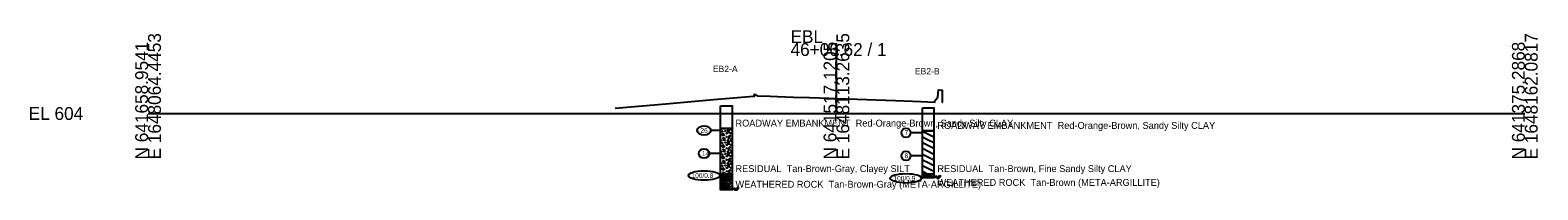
# Model space of a CAD drawing. Extents: x -26 to 303, y -74 to 518.
# Drawn here: x -25.7 to 302.8, y 483.4 to 518.1 of the extents above; entities that cross this region are included whole.
import ezdxf

# ---------------------------------------------------------------- set-up
doc = ezdxf.new("R2010")
doc.units = 0
for name, color, linetype in [('Exist Cross Section Cell', 7, 'Continuous'), ('Exist XS Ground Line', 7, 'Continuous'), ('Prop Road Sect_ Boring - Header Labels from Geopak', 7, 'Continuous'), ('Prop Road Sect_ Boring - Material (Desc Tx)', 7, 'Continuous'), ('Prop Road Sect_ Boring - Material (Outline)', 7, 'Continuous'), ('Prop Road Sect_ Boring - Peripheral (HR Indicator)', 7, 'Continuous'), ('Prop Road Sect_ Boring - Peripheral (SPT Oval + Leader)', 7, 'Continuous'), ('Prop Road Sect_ Boring - Peripheral (SPT Tx)', 7, 'Continuous')]:
    doc.layers.add(name, color=color, linetype=linetype)

msp = doc.modelspace()

# ---------------------------------------------------------------- linework, layer by layer
at = {"layer": 'Exist Cross Section Cell'}
for p, q in [((150, 500), (150, 515.32)), ((0, 500), (150, 500)), ((150, 500), (300, 500))]:
    msp.add_line(p, q, dxfattribs=at)
at = {"layer": 'Exist XS Ground Line'}
msp.add_lwpolyline([(101.79, 501.17), (112.83, 502.12), (123.23, 503.02), (126.72, 503.32), (131.08, 503.7), (131.75, 503.75), (132.14, 503.79), (132.14, 504.19), (132.85, 503.85), (135.59, 503.75), (137.14, 503.7), (140.61, 503.57), (144.15, 503.45), (148.37, 503.3), (150, 503.24), (150, 503.24), (154.5, 503.09), (162.86, 502.79), (168.39, 502.6), (171.44, 502.49), (171.44, 502.74), (172.06, 503.52), (172.24, 505.11), (173.04, 505.1), (173.05, 502.43), (173.18, 502.43)], dxfattribs=at)
msp.add_lwpolyline([(101.79, 501.17), (112.83, 502.12), (123.23, 503.02), (126.72, 503.32), (131.08, 503.7), (131.75, 503.75), (132.14, 503.79), (132.14, 504.19), (132.85, 503.85), (135.59, 503.75), (137.14, 503.7), (140.61, 503.57), (144.15, 503.45), (148.37, 503.3), (150, 503.24), (150, 503.24), (154.5, 503.09), (162.86, 502.79), (168.39, 502.6), (171.44, 502.49), (171.44, 502.74), (172.06, 503.52), (172.24, 505.11), (173.04, 505.1), (173.05, 502.43), (173.18, 502.43)], dxfattribs=at)
at = {"layer": 'Prop Road Sect_ Boring - Material (Outline)'}
for p, q in [((125.32, 496.7), (125.25, 496.62)), ((125.32, 496.7), (125.25, 496.62)), ((125.65, 496.48), (125.65, 496.7)), ((125.65, 496.48), (125.65, 496.7)), ((168.75, 496.17), (171.25, 494.92)), ((168.75, 496.17), (171.25, 494.92)), ((168.75, 496.17), (171.25, 494.92)), ((168.75, 496.17), (171.25, 494.92)), ((171.18, 496.2), (171.25, 496.17)), ((171.18, 496.2), (171.25, 496.17)), ((171.25, 496.17), (171.25, 496.16)), ((171.25, 496.17), (171.25, 496.16)), ((171.25, 496.17), (171.25, 496.16)), ((171.25, 496.17), (171.25, 496.16)), ((125.39, 494.29), (125.25, 494.12)), ((125.39, 494.29), (125.25, 494.12)), ((125.65, 493.98), (125.65, 494.29)), ((125.65, 493.98), (125.65, 494.29)), ((168.75, 494.92), (170, 494.29)), ((168.75, 494.92), (170, 494.29)), ((168.75, 493.67), (171.25, 492.42)), ((168.75, 493.67), (171.25, 492.42)), ((168.75, 493.67), (171.25, 492.42)), ((168.75, 493.67), (171.25, 492.42)), ((170, 494.29), (171.25, 493.67)), ((170, 494.29), (171.25, 493.67)), ((171.25, 494.92), (171.25, 494.92)), ((171.25, 494.92), (171.25, 494.92)), ((171.25, 493.67), (171.25, 493.67)), ((171.25, 493.67), (171.25, 493.67)), ((171.25, 493.67), (171.25, 493.67)), ((171.25, 493.67), (171.25, 493.67)), ((125.39, 491.8), (125.25, 491.63)), ((125.39, 491.8), (125.25, 491.63)), ((125.65, 491.48), (125.65, 491.8)), ((125.65, 491.48), (125.65, 491.8)), ((168.75, 492.42), (170, 491.8)), ((168.75, 492.42), (170, 491.8)), ((168.75, 491.17), (171.25, 489.92)), ((168.75, 491.17), (171.25, 489.92)), ((168.75, 491.17), (171.25, 489.92)), ((168.75, 491.17), (171.25, 489.92)), ((168.75, 489.92), (170, 489.3)), ((168.75, 489.92), (170, 489.3)), ((170, 491.8), (171.25, 491.17)), ((170, 491.8), (171.25, 491.17)), ((171.25, 492.42), (171.25, 492.42)), ((171.25, 492.42), (171.25, 492.42)), ((171.25, 491.17), (171.25, 491.17)), ((171.25, 491.17), (171.25, 491.17)), ((171.25, 491.17), (171.25, 491.17)), ((171.25, 491.17), (171.25, 491.17)), ((171.25, 489.92), (171.25, 489.92)), ((171.25, 489.92), (171.25, 489.92)), ((124.83, 486.8), (124.75, 486.76)), ((124.83, 486.8), (124.75, 486.76)), ((124.79, 486.6), (125.01, 486.6)), ((124.79, 486.6), (125.01, 486.6)), ((124.79, 486.51), (124.99, 486.51)), ((124.79, 486.51), (124.99, 486.51)), ((124.94, 486.74), (124.85, 486.8)), ((124.94, 486.74), (124.85, 486.8)), ((125.39, 489.3), (125.25, 489.13)), ((125.39, 489.3), (125.25, 489.13)), ((125.65, 488.98), (125.65, 489.3)), ((125.65, 488.98), (125.65, 489.3)), ((126.34, 486.68), (126.84, 486.68)), ((126.34, 486.68), (126.84, 486.68)), ((126.41, 486.57), (126.81, 486.57)), ((126.41, 486.57), (126.81, 486.57)), ((126.46, 486.46), (126.74, 486.46)), ((126.46, 486.46), (126.74, 486.46)), ((127.25, 486.76), (127.25, 486.76)), ((127.25, 486.76), (127.25, 486.76)), ((168.75, 488.67), (171.25, 487.42)), ((168.75, 488.67), (171.25, 487.42)), ((168.75, 488.67), (171.25, 487.42)), ((168.75, 488.67), (171.25, 487.42)), ((168.75, 487.42), (170, 486.8)), ((168.75, 487.42), (170, 486.8)), ((168.75, 486.11), (169.32, 486.24)), ((168.75, 486.11), (169.32, 486.24)), ((168.79, 486.7), (169.01, 486.7)), ((168.79, 486.7), (169.01, 486.7)), ((168.79, 486.61), (168.99, 486.61)), ((168.79, 486.61), (168.99, 486.61)), ((169.32, 486.24), (168.89, 486)), ((169.32, 486.24), (168.89, 486)), ((170.29, 486.25), (169.65, 486)), ((170.29, 486.25), (169.65, 486)), ((170.58, 486.25), (169.94, 486)), ((170.58, 486.25), (169.94, 486)), ((170, 489.3), (171.25, 488.67)), ((170, 489.3), (171.25, 488.67)), ((170.09, 486.25), (170.29, 486.25)), ((170.09, 486.25), (170.29, 486.25)), ((170.58, 486.25), (170.11, 486)), ((170.58, 486.25), (170.11, 486)), ((170.34, 486.78), (170.84, 486.78)), ((170.34, 486.78), (170.84, 486.78)), ((170.41, 486.67), (170.81, 486.67)), ((170.41, 486.67), (170.81, 486.67)), ((170.46, 486.56), (170.74, 486.56)), ((170.46, 486.56), (170.74, 486.56)), ((171.25, 488.67), (171.25, 488.67)), ((171.25, 488.67), (171.25, 488.67)), ((171.25, 488.67), (171.25, 488.67)), ((171.25, 488.67), (171.25, 488.67)), ((171.25, 487.42), (171.25, 487.42)), ((171.25, 487.42), (171.25, 487.42)), ((171.25, 486.26), (171.25, 486.27)), ((171.25, 486.26), (171.25, 486.27)), ((124.75, 486), (125.32, 486.14)), ((124.75, 486), (125.32, 486.14)), ((124.86, 484.85), (124.75, 484.94)), ((124.86, 484.85), (124.75, 484.94)), ((124.75, 483.51), (125.32, 483.64)), ((124.75, 483.51), (125.32, 483.64)), ((124.79, 484.1), (125.01, 484.1)), ((124.79, 484.1), (125.01, 484.1)), ((124.79, 484.01), (124.99, 484.01)), ((124.79, 484.01), (124.99, 484.01)), ((125.32, 486.14), (124.89, 485.9)), ((125.32, 486.14), (124.89, 485.9)), ((125.32, 483.64), (124.89, 483.4)), ((125.32, 483.64), (124.89, 483.4)), ((125.19, 485.84), (125.21, 485.9)), ((125.19, 485.84), (125.21, 485.9)), ((125.37, 485.28), (125.56, 485.28)), ((125.37, 485.28), (125.56, 485.28)), ((125.39, 485.34), (125.6, 485.34)), ((125.39, 485.34), (125.6, 485.34)), ((125.39, 485.22), (125.61, 485.22)), ((125.39, 485.22), (125.61, 485.22)), ((125.42, 485.39), (125.69, 485.39)), ((125.42, 485.39), (125.69, 485.39)), ((125.59, 485.84), (125.65, 485.9)), ((125.59, 485.84), (125.65, 485.9)), ((126.29, 486.14), (125.65, 485.9)), ((126.29, 486.14), (125.65, 485.9)), ((126.29, 483.65), (125.65, 483.4)), ((126.29, 483.65), (125.65, 483.4)), ((125.69, 486.02), (125.97, 486.02)), ((125.69, 486.02), (125.97, 486.02)), ((125.69, 483.53), (125.97, 483.53)), ((125.69, 483.53), (125.97, 483.53)), ((125.87, 486.09), (126.15, 486.09)), ((125.87, 486.09), (126.15, 486.09)), ((125.87, 483.59), (126.15, 483.59)), ((125.87, 483.59), (126.15, 483.59)), ((126.58, 486.14), (125.94, 485.9)), ((126.58, 486.14), (125.94, 485.9)), ((126.58, 483.65), (125.94, 483.4)), ((126.58, 483.65), (125.94, 483.4)), ((126.04, 485.84), (126.11, 485.9)), ((126.04, 485.84), (126.11, 485.9)), ((126.09, 486.14), (126.29, 486.14)), ((126.09, 486.14), (126.29, 486.14)), ((126.09, 483.65), (126.29, 483.65)), ((126.09, 483.65), (126.29, 483.65)), ((126.58, 486.14), (126.11, 485.9)), ((126.58, 486.14), (126.11, 485.9)), ((126.58, 483.65), (126.11, 483.4)), ((126.58, 483.65), (126.11, 483.4)), ((126.26, 484.66), (126.54, 484.66)), ((126.26, 484.66), (126.54, 484.66)), ((126.26, 484.58), (126.51, 484.58)), ((126.26, 484.58), (126.51, 484.58)), ((126.31, 484.49), (126.49, 484.49)), ((126.31, 484.49), (126.49, 484.49)), ((126.34, 484.18), (126.84, 484.18)), ((126.34, 484.18), (126.84, 484.18)), ((126.41, 484.07), (126.81, 484.07)), ((126.41, 484.07), (126.81, 484.07)), ((126.46, 483.96), (126.74, 483.96)), ((126.46, 483.96), (126.74, 483.96)), ((127.25, 485.93), (127.13, 485.9)), ((127.25, 485.93), (127.13, 485.9)), ((127.25, 483.43), (127.13, 483.4)), ((127.25, 483.43), (127.13, 483.4)), ((127.25, 486.16), (127.25, 486.16)), ((127.25, 486.16), (127.25, 486.16)), ((127.25, 486), (127.25, 486.01)), ((127.25, 486), (127.25, 486.01)), ((127.25, 485.47), (127.25, 485.47)), ((127.25, 485.47), (127.25, 485.47)), ((127.25, 484.94), (127.25, 484.94)), ((127.25, 484.94), (127.25, 484.94)), ((127.25, 484.26), (127.25, 484.26)), ((127.25, 484.26), (127.25, 484.26)), ((127.25, 483.66), (127.25, 483.67)), ((127.25, 483.66), (127.25, 483.67)), ((127.25, 483.51), (127.25, 483.51)), ((127.25, 483.51), (127.25, 483.51)), ((169.69, 486.13), (169.97, 486.13)), ((169.69, 486.13), (169.97, 486.13)), ((169.87, 486.19), (170.15, 486.19)), ((169.87, 486.19), (170.15, 486.19)), ((171.25, 486.03), (171.13, 486)), ((171.25, 486.03), (171.13, 486)), ((171.25, 486.11), (171.25, 486.11)), ((171.25, 486.11), (171.25, 486.11))]:
    msp.add_line(p, q, dxfattribs=at)
for points in [[(124.75, 501.7), (127.25, 501.7), (127.25, 496.7), (124.75, 496.7)], [(168.75, 501.2), (171.25, 501.2), (171.25, 496.2), (168.75, 496.2)], [(124.75, 496.7), (127.25, 496.7), (127.25, 486.8), (124.75, 486.8)], [(168.75, 496.2), (171.25, 496.2), (171.25, 486.8), (168.75, 486.8)], [(124.75, 486.8), (127.25, 486.8), (127.25, 483.4), (124.75, 483.4)], [(168.75, 486.8), (171.25, 486.8), (171.25, 486), (168.75, 486)]]:
    msp.add_lwpolyline(points, close=True, dxfattribs=at)
for points in [[(126.58, 496.48), (126.58, 495.86), (126.14, 496.3)], [(126.58, 496.48), (126.58, 495.86), (126.14, 496.3)], [(125.29, 495.06), (125.29, 495.68), (125.69, 495.2)], [(125.29, 495.06), (125.29, 495.68), (125.69, 495.2)], [(125.29, 492.56), (125.29, 493.18), (125.69, 492.7)], [(125.29, 492.56), (125.29, 493.18), (125.69, 492.7)], [(125.65, 494.29), (125.65, 494.6), (125.39, 494.29)], [(125.65, 494.29), (125.65, 494.6), (125.39, 494.29)], [(126.58, 493.99), (126.58, 493.36), (126.14, 493.8)], [(126.58, 493.99), (126.58, 493.36), (126.14, 493.8)], [(126.47, 495.06), (126.47, 494.43), (126.91, 494.87)], [(126.47, 495.06), (126.47, 494.43), (126.91, 494.87)], [(125.29, 490.06), (125.29, 490.69), (125.69, 490.21)], [(125.29, 490.06), (125.29, 490.69), (125.69, 490.21)], [(125.65, 491.8), (125.65, 492.11), (125.39, 491.8)], [(125.65, 491.8), (125.65, 492.11), (125.39, 491.8)], [(125.65, 489.3), (125.65, 489.61), (125.39, 489.3)], [(125.65, 489.3), (125.65, 489.61), (125.39, 489.3)], [(126.58, 491.49), (126.58, 490.86), (126.14, 491.31)], [(126.58, 491.49), (126.58, 490.86), (126.14, 491.31)], [(126.47, 492.56), (126.47, 491.93), (126.91, 492.38)], [(126.47, 492.56), (126.47, 491.93), (126.91, 492.38)], [(126.47, 490.06), (126.47, 489.44), (126.91, 489.88)], [(126.47, 490.06), (126.47, 489.44), (126.91, 489.88)], [(124.75, 486.16), (125.02, 486.26), (125.4, 486.38), (125.84, 486.53), (125.79, 486.41), (125.75, 486.36), (126.34, 486.51)], [(124.75, 486.16), (125.02, 486.26), (125.4, 486.38), (125.84, 486.53), (125.79, 486.41), (125.75, 486.36), (126.34, 486.51)], [(125.27, 486.8), (125.14, 486.65), (125.09, 486.62), (124.94, 486.74)], [(125.27, 486.8), (125.14, 486.65), (125.09, 486.62), (124.94, 486.74)], [(125.21, 485.9), (125.64, 486.2), (126.34, 486.37), (126.71, 486.43), (127.14, 486.68), (127.25, 486.76)], [(125.21, 485.9), (125.64, 486.2), (126.34, 486.37), (126.71, 486.43), (127.14, 486.68), (127.25, 486.76)], [(125.29, 487.56), (125.29, 488.19), (125.69, 487.71)], [(125.29, 487.56), (125.29, 488.19), (125.69, 487.71)], [(125.65, 486.8), (125.65, 487.11), (125.39, 486.8)], [(125.65, 486.8), (125.65, 487.11), (125.39, 486.8)], [(125.57, 486.8), (125.56, 486.79), (125.54, 486.76), (125.56, 486.74), (125.74, 486.79), (125.76, 486.8)], [(125.57, 486.8), (125.56, 486.79), (125.54, 486.76), (125.56, 486.74), (125.74, 486.79), (125.76, 486.8)], [(126.58, 488.99), (126.58, 488.37), (126.14, 488.81)], [(126.58, 488.99), (126.58, 488.37), (126.14, 488.81)], [(126.47, 487.56), (126.47, 486.94), (126.91, 487.38)], [(126.47, 487.56), (126.47, 486.94), (126.91, 487.38)], [(168.75, 486.26), (169.02, 486.36), (169.4, 486.48), (169.84, 486.63), (169.79, 486.51), (169.75, 486.46), (170.34, 486.62)], [(168.75, 486.26), (169.02, 486.36), (169.4, 486.48), (169.84, 486.63), (169.79, 486.51), (169.75, 486.46), (170.34, 486.62)], [(169.18, 486.8), (169.14, 486.75), (169.09, 486.73), (168.99, 486.8)], [(169.18, 486.8), (169.14, 486.75), (169.09, 486.73), (168.99, 486.8)], [(169.21, 486), (169.64, 486.3), (170.34, 486.47), (170.71, 486.53), (171.14, 486.78), (171.16, 486.8)], [(169.21, 486), (169.64, 486.3), (170.34, 486.47), (170.71, 486.53), (171.14, 486.78), (171.16, 486.8)], [(171.25, 486.26), (171.19, 486.25), (170.86, 486.16), (170.8, 486)], [(171.25, 486.26), (171.19, 486.25), (170.86, 486.16), (170.8, 486)], [(124.97, 485.44), (124.87, 485.49), (124.8, 485.49), (124.75, 485.47)], [(124.97, 485.44), (124.87, 485.49), (124.8, 485.49), (124.75, 485.47)], [(124.94, 484.24), (124.85, 484.31), (124.75, 484.26)], [(124.94, 484.24), (124.85, 484.31), (124.75, 484.26)], [(124.75, 483.66), (125.02, 483.76), (125.4, 483.88), (125.84, 484.03), (125.79, 483.91), (125.75, 483.86), (126.34, 484.02)], [(124.75, 483.66), (125.02, 483.76), (125.4, 483.88), (125.84, 484.03), (125.79, 483.91), (125.75, 483.86), (126.34, 484.02)], [(126.04, 485.84), (125.69, 485.48), (125.61, 485.42), (125.44, 485.42), (125.36, 485.31), (125.39, 485.22), (125.41, 485.17), (125.29, 485.08), (125.29, 485.03), (125.29, 485.03), (125.21, 485), (125.16, 484.97), (125.16, 484.8), (125.11, 484.66), (125.04, 484.52), (124.99, 484.55), (124.91, 484.75), (124.86, 484.85)], [(126.04, 485.84), (125.69, 485.48), (125.61, 485.42), (125.44, 485.42), (125.36, 485.31), (125.39, 485.22), (125.41, 485.17), (125.29, 485.08), (125.29, 485.03), (125.29, 485.03), (125.21, 485), (125.16, 484.97), (125.16, 484.8), (125.11, 484.66), (125.04, 484.52), (124.99, 484.55), (124.91, 484.75), (124.86, 484.85)], [(124.94, 485.76), (124.89, 485.81), (124.89, 485.9)], [(124.94, 485.76), (124.89, 485.81), (124.89, 485.9)], [(124.94, 485.76), (124.96, 485.73), (125.01, 485.67), (125.04, 485.73), (125.06, 485.67), (125.09, 485.67), (125.11, 485.73), (125.16, 485.76), (125.19, 485.84)], [(124.94, 485.76), (124.96, 485.73), (125.01, 485.67), (125.04, 485.73), (125.06, 485.67), (125.09, 485.67), (125.11, 485.73), (125.16, 485.76), (125.19, 485.84)], [(126.54, 485.79), (126.09, 485.45), (125.91, 485.2), (125.84, 485.05), (125.71, 484.89), (125.56, 484.72), (125.41, 484.52), (125.31, 484.35), (125.14, 484.15), (125.09, 484.13), (124.94, 484.24)], [(126.54, 485.79), (126.09, 485.45), (125.91, 485.2), (125.84, 485.05), (125.71, 484.89), (125.56, 484.72), (125.41, 484.52), (125.31, 484.35), (125.14, 484.15), (125.09, 484.13), (124.94, 484.24)], [(124.97, 485.44), (125.04, 485.39), (125.04, 485.25), (125.19, 485.39), (125.24, 485.67), (125.36, 485.81), (125.59, 485.84)], [(124.97, 485.44), (125.04, 485.39), (125.04, 485.25), (125.19, 485.39), (125.24, 485.67), (125.36, 485.81), (125.59, 485.84)], [(125.21, 483.4), (125.64, 483.7), (126.34, 483.87), (126.71, 483.93), (127.14, 484.18), (127.25, 484.26)], [(125.21, 483.4), (125.64, 483.7), (126.34, 483.87), (126.71, 483.93), (127.14, 484.18), (127.25, 484.26)], [(125.94, 485.9), (125.86, 485.82), (125.81, 485.79), (125.7, 485.72), (125.62, 485.65), (125.51, 485.51), (125.44, 485.42)], [(125.94, 485.9), (125.86, 485.82), (125.81, 485.79), (125.7, 485.72), (125.62, 485.65), (125.51, 485.51), (125.44, 485.42)], [(126.64, 485.56), (126.19, 485.14), (126.01, 484.94), (125.99, 484.8), (125.91, 484.63), (125.84, 484.52), (125.56, 484.3), (125.54, 484.27), (125.56, 484.24), (125.74, 484.3), (125.86, 484.35), (126.16, 484.44), (126.19, 484.41), (126.56, 484.46), (126.79, 484.63), (126.89, 484.81)], [(126.64, 485.56), (126.19, 485.14), (126.01, 484.94), (125.99, 484.8), (125.91, 484.63), (125.84, 484.52), (125.56, 484.3), (125.54, 484.27), (125.56, 484.24), (125.74, 484.3), (125.86, 484.35), (126.16, 484.44), (126.19, 484.41), (126.56, 484.46), (126.79, 484.63), (126.89, 484.81)], [(126.54, 485.79), (126.59, 485.8), (126.66, 485.82), (126.74, 485.85), (126.8, 485.9)], [(126.54, 485.79), (126.59, 485.8), (126.66, 485.82), (126.74, 485.85), (126.8, 485.9)], [(127.25, 485.72), (127.11, 485.62), (126.91, 485.45), (126.79, 485.28), (126.61, 485.05), (126.79, 485.17), (126.99, 485.36), (127.09, 485.48), (127.14, 485.42), (127.19, 485.42), (127.25, 485.47)], [(127.25, 485.72), (127.11, 485.62), (126.91, 485.45), (126.79, 485.28), (126.61, 485.05), (126.79, 485.17), (126.99, 485.36), (127.09, 485.48), (127.14, 485.42), (127.19, 485.42), (127.25, 485.47)], [(126.64, 485.56), (126.79, 485.65), (126.84, 485.73), (126.99, 485.81), (127.04, 485.84)], [(126.64, 485.56), (126.79, 485.65), (126.84, 485.73), (126.99, 485.81), (127.04, 485.84)], [(127.25, 486.16), (127.19, 486.15), (126.86, 486.06), (126.8, 485.9)], [(127.25, 486.16), (127.19, 486.15), (126.86, 486.06), (126.8, 485.9)], [(127.25, 483.66), (127.19, 483.65), (126.86, 483.56), (126.8, 483.4)], [(127.25, 483.66), (127.19, 483.65), (126.86, 483.56), (126.8, 483.4)], [(126.89, 484.81), (126.97, 484.89), (127.11, 484.93), (127.25, 484.95)], [(126.89, 484.81), (126.97, 484.89), (127.11, 484.93), (127.25, 484.95)], [(127.04, 485.84), (127.07, 485.86), (127.13, 485.9)], [(127.04, 485.84), (127.07, 485.86), (127.13, 485.9)]]:
    msp.add_lwpolyline(points, dxfattribs=at)
for centre, radius in [((125.1, 496.09), 0.075), ((125.1, 496.09), 0.075), ((125.76, 496.16), 0.05), ((125.76, 496.16), 0.05), ((126.94, 496.51), 0.05), ((126.94, 496.51), 0.05), ((124.91, 494.15), 0.05), ((124.91, 494.15), 0.05), ((124.95, 495.46), 0.075), ((124.95, 495.46), 0.075), ((124.95, 492.96), 0.075), ((124.95, 492.96), 0.075), ((125.1, 493.59), 0.075), ((125.1, 493.59), 0.075), ((125.35, 494.64), 0.075), ((125.35, 494.64), 0.075), ((125.76, 493.66), 0.05), ((125.76, 493.66), 0.05), ((126.08, 494.92), 0.05), ((126.08, 494.92), 0.05), ((126.12, 495.68), 0.075), ((126.12, 495.68), 0.075), ((126.12, 493.18), 0.075), ((126.12, 493.18), 0.075), ((126.32, 494.16), 0.075), ((126.32, 494.16), 0.075), ((126.78, 495.14), 0.075), ((126.78, 495.14), 0.075), ((126.94, 494.01), 0.05), ((126.94, 494.01), 0.05), ((127, 495.71), 0.075), ((127, 495.71), 0.075), ((127, 493.21), 0.075), ((127, 493.21), 0.075), ((127.1, 494.41), 0.05), ((127.1, 494.41), 0.05), ((124.91, 491.66), 0.05), ((124.91, 491.66), 0.05), ((124.95, 490.46), 0.075), ((124.95, 490.46), 0.075), ((125.1, 491.1), 0.075), ((125.1, 491.1), 0.075), ((125.35, 492.14), 0.075), ((125.35, 492.14), 0.075), ((125.35, 489.64), 0.075), ((125.35, 489.64), 0.075), ((125.76, 491.16), 0.05), ((125.76, 491.16), 0.05), ((126.08, 492.42), 0.05), ((126.08, 492.42), 0.05), ((126.08, 489.92), 0.05), ((126.08, 489.92), 0.05), ((126.12, 490.69), 0.075), ((126.12, 490.69), 0.075), ((126.32, 491.66), 0.075), ((126.32, 491.66), 0.075), ((126.78, 492.64), 0.075), ((126.78, 492.64), 0.075), ((126.78, 490.14), 0.075), ((126.78, 490.14), 0.075), ((126.94, 491.51), 0.05), ((126.94, 491.51), 0.05), ((127, 490.71), 0.075), ((127, 490.71), 0.075), ((127.1, 491.91), 0.05), ((127.1, 491.91), 0.05), ((124.91, 489.16), 0.05), ((124.91, 489.16), 0.05), ((124.95, 487.96), 0.075), ((124.95, 487.96), 0.075), ((125.1, 488.6), 0.075), ((125.1, 488.6), 0.075), ((125.35, 487.15), 0.075), ((125.35, 487.15), 0.075), ((125.76, 488.66), 0.05), ((125.76, 488.66), 0.05), ((126.08, 487.42), 0.05), ((126.08, 487.42), 0.05), ((126.12, 488.19), 0.075), ((126.12, 488.19), 0.075), ((126.32, 489.16), 0.075), ((126.32, 489.16), 0.075), ((126.78, 487.64), 0.075), ((126.78, 487.64), 0.075), ((126.94, 489.01), 0.05), ((126.94, 489.01), 0.05), ((127, 488.21), 0.075), ((127, 488.21), 0.075), ((127.1, 489.41), 0.05), ((127.1, 489.41), 0.05), ((127.1, 486.92), 0.05), ((127.1, 486.92), 0.05)]:
    msp.add_circle(centre, radius, dxfattribs=at)
for centre, radius, start, end in [((124.91, 496.65), 0.05, 101.4052, 78.5948), ((124.91, 496.65), 0.05, 101.4052, 78.5948), ((126.32, 496.65), 0.075, 143.1268, 36.8732), ((126.32, 496.65), 0.075, 143.1268, 36.8732)]:
    msp.add_arc(centre, radius, start, end, dxfattribs=at)
at = {"layer": 'Prop Road Sect_ Boring - Peripheral (HR Indicator)'}
for p, q in [((171, 486), (171.36, 486.48)), ((171.3, 486), (171.66, 486.48)), ((171.6, 486), (171.96, 486.48)), ((172.04, 486.24), (172.64, 486.24)), ((172.21, 486.46), (172.81, 486.46)), ((127, 483.4), (127.36, 483.88)), ((127.3, 483.4), (127.66, 483.88)), ((127.6, 483.4), (127.96, 483.88)), ((127.87, 483.42), (128.47, 483.42)), ((128.04, 483.64), (128.64, 483.64)), ((128.21, 483.86), (128.81, 483.86)), ((171.87, 486.02), (172.47, 486.02))]:
    msp.add_line(p, q, dxfattribs=at)
at = {"layer": 'Prop Road Sect_ Boring - Peripheral (SPT Oval + Leader)'}
for p, q in [((124.75, 496.3), (122.62, 496.3)), ((168.75, 495.8), (166.14, 495.8)), ((124.75, 491.3), (122.31, 491.3)), ((168.75, 490.8), (166.14, 490.8)), ((124.75, 486.5), (124.56, 486.5)), ((168.75, 485.9), (168.56, 485.9))]:
    msp.add_line(p, q, dxfattribs=at)
for centre, major_axis, ratio in [((121.15, 496.3), (1.47, 0), 0.695008), ((165.15, 495.8), (0, 1.02), 0.966391), ((121.15, 491.3), (1.16, 0), 0.883591), ((165.15, 490.8), (0, 1.02), 0.966391), ((121.15, 486.5), (3.41, 0), 0.300427), ((165.15, 485.9), (3.41, 0), 0.300427)]:
    msp.add_ellipse(centre, major_axis=major_axis, ratio=ratio, dxfattribs=at)

# ---------------------------------------------------------------- texts
at = {"layer": 'Exist Cross Section Cell'}
for s, p in [('E 1648064.4453', (2.8, 490)), ('E 1648113.2635', (152.8, 490)), ('E 1648162.0817', (302.8, 490)), ('N 641658.9541', (0, 490)), ('N 641517.1205', (150, 490)), ('N 641375.2868', (300, 490))]:
    msp.add_text(s, height=2.8, rotation=90, dxfattribs=at).set_placement(p)
for s, p in [('EBL', (140, 515.32)), ('46+06.62 / 1', (140, 512.52)), ('EL 604', (-26, 498.6))]:
    msp.add_text(s, height=2.8, dxfattribs=at).set_placement(p)
at = {"layer": 'Prop Road Sect_ Boring - Header Labels from Geopak'}
for s, p in [('EB2-A', (123.06, 509)), ('EB2-B', (167.08, 508.5))]:
    msp.add_text(s, height=1.4, dxfattribs=at).set_placement(p)
at = {"layer": 'Prop Road Sect_ Boring - Material (Desc Tx)'}
for s, p in [('ROADWAY EMBANKMENT  Red-Orange-Brown, Sandy Silty CLAY', (128, 497.15)), ('ROADWAY EMBANKMENT  Red-Orange-Brown, Sandy Silty CLAY', (172, 496.65)), ('RESIDUAL  Tan-Brown-Gray, Clayey SILT', (128, 487.25)), ('RESIDUAL  Tan-Brown, Fine Sandy Silty CLAY', (172, 487.25)), ('WEATHERED ROCK  Tan-Brown-Gray (META-ARGILLITE)', (128, 483.85)), ('WEATHERED ROCK  Tan-Brown (META-ARGILLITE)', (172, 484.25))]:
    msp.add_text(s, height=1.5, dxfattribs=at).set_placement(p)
at = {"layer": 'Prop Road Sect_ Boring - Peripheral (SPT Tx)'}
for s, height, p in [('26', 1.025, (120.38, 495.79)), ('7', 1.02, (164.86, 495.29)), ('14', 1.025, (120.69, 490.79)), ('8', 1.02, (164.86, 490.29)), ('100/0.8', 1.025, (118.44, 485.99)), ('100/0.9', 1.025, (162.44, 485.39))]:
    msp.add_text(s, height=height, dxfattribs=at).set_placement(p)

doc.saveas('drawing.dxf')
